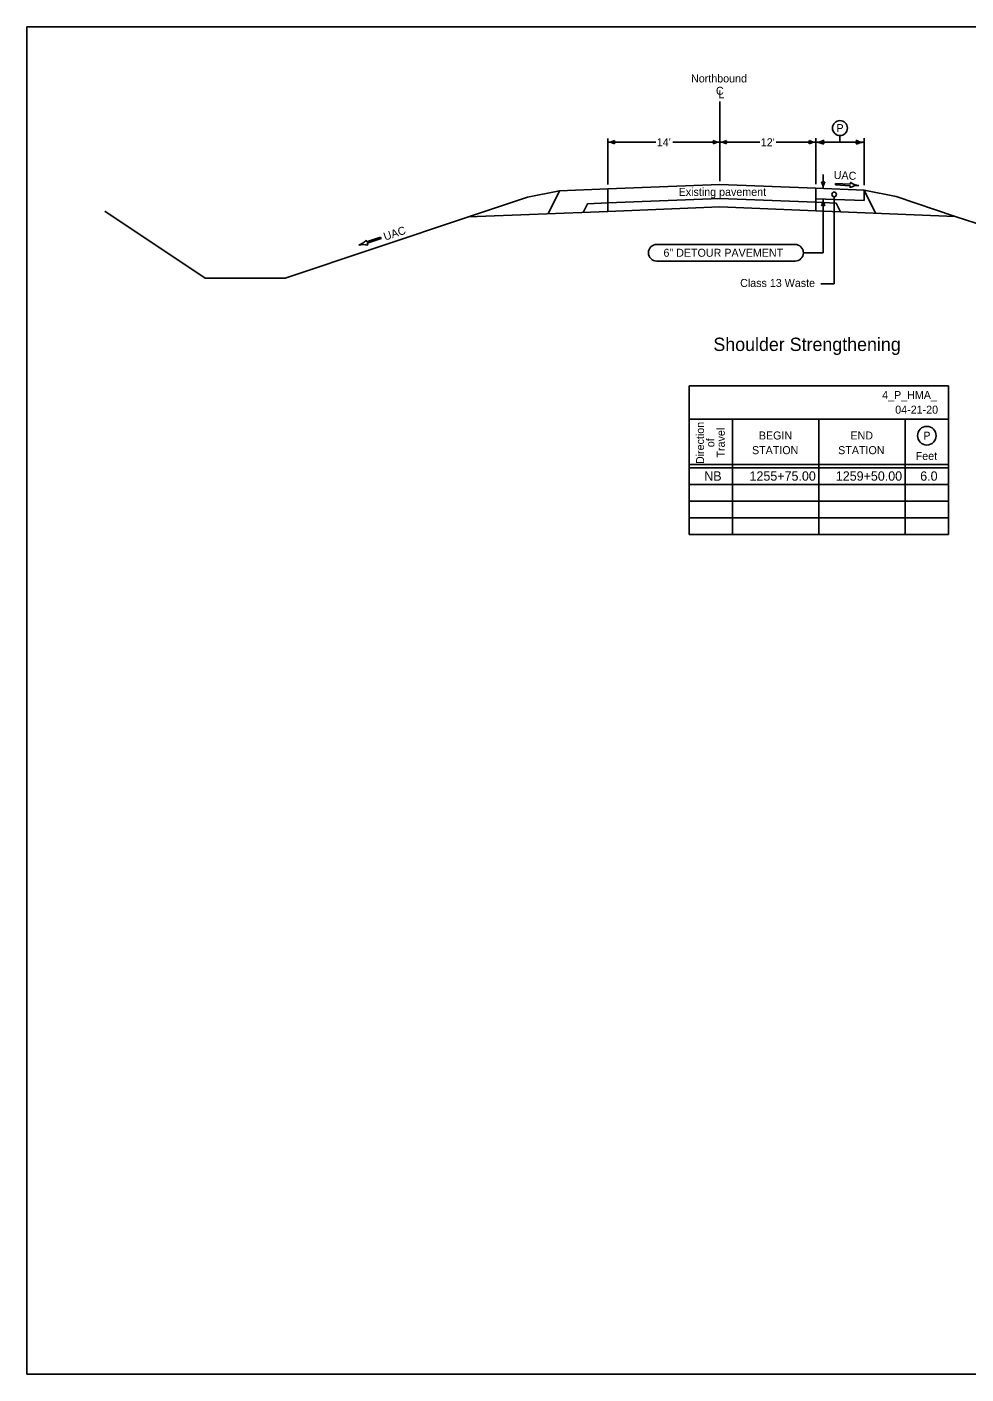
# Model space of a CAD drawing. Extents: x 10133 to 81668, y 7924 to 11018.
# Drawn here: x 10133 to 11541, y 7924 to 9944 of the extents above; entities that cross this region are included whole.
import ezdxf

# ---------------------------------------------------------------- set-up
doc = ezdxf.new("R2010")
doc.units = 0
for name, color, linetype in [('dsnCellsNorthArrow', 7, 'Continuous'), ('DsnShtRevisedText', 7, 'Continuous'), ('dsnStdNameDate', 7, 'Continuous'), ('dsnStdTable', 7, 'Continuous'), ('dsnTextFinalPlan', 7, 'Continuous'), ('dsnTextTabulation', 7, 'Continuous'), ('dsnXsPCCPavementBottom', 7, 'Continuous'), ('dsnXsShldrEarthFill', 7, 'Continuous'), ('dsnXsShldrSpecialBackBottom', 7, 'Continuous'), ('Level 6', 7, 'Continuous'), ('Level 7', 7, 'Continuous'), ('Level 8', 7, 'Continuous'), ('SheetAddendum', 7, 'Continuous'), ('SheetBorder', 7, 'Continuous')]:
    doc.layers.add(name, color=color, linetype=linetype)

# ---------------------------------------------------------------- blocks, each defined once
blk = doc.blocks.new('LT')
at = {"layer": 'dsnCellsNorthArrow'}
for centre, radius, start, end in [((-35.6, 0), 16.4, 342.2666, 17.7333), ((0, 42.5), 42.5, 241.9275, 270), ((0, -42.5), 42.5, 90, 118.0725)]:
    blk.add_arc(centre, radius, start, end, dxfattribs=at)

msp = doc.modelspace()

# ---------------------------------------------------------------- linework, layer by layer
at = {"layer": 'DsnShtRevisedText'}
for p, q in [((11345.7, 9709.5), (11345.6, 9707.1)), ((11345.6, 9707.1), (11367.6, 9705.8)), ((11367.7, 9708.2), (11345.7, 9709.5)), ((11367.6, 9705.8), (11367.4, 9703)), ((11367.9, 9711), (11367.7, 9708.2)), ((11380.4, 9706.3), (11380.4, 9706.3)), ((11343.6, 9558.7), (11343.6, 9689.4)), ((11077.4, 9617.9), (11284.9, 9617.9)), ((11284.9, 9617.9), (11077.4, 9617.9)), ((11284.9, 9592.9), (11077.4, 9592.9)), ((11284.9, 9592.9), (11077.4, 9592.9)), ((11323.4, 9558.7), (11343.6, 9558.7))]:
    msp.add_line(p, q, dxfattribs=at)
msp.add_circle((11343.6, 9692.9), 3.5, dxfattribs=at)
for centre, radius, start, end in [((11380, 9680.5), 25.8, 89.1159, 119.146), ((11382.9, 9732), 25.8, 234.3819, 264.4119), ((11077.4, 9605.4), 12.5, 90, 270), ((11077.4, 9605.4), 12.5, 90, 270), ((11284.9, 9605.4), 12.5, 270, 90), ((11284.9, 9605.4), 12.5, 270, 90)]:
    msp.add_arc(centre, radius, start, end, dxfattribs=at)
at = {"layer": 'dsnStdNameDate'}
for p, q in [((11316.1, 9702.1), (11388.5, 9699.2)), ((11316.1, 9702.1), (11316.1, 9686.4)), ((11388.5, 9699.2), (11388.5, 9683.6)), ((11316.1, 9686.4), (11388.5, 9683.6))]:
    msp.add_line(p, q, dxfattribs=at)
at = {"layer": 'dsnStdTable'}
for p, q in [((11126, 9183.1), (11126, 9406.1)), ((11126, 9406.1), (11515.3, 9406.1)), ((11515.3, 9183.1), (11515.3, 9406.1)), ((11126, 9356.1), (11515.3, 9356.1)), ((11191.3, 9183.1), (11191.3, 9356.1)), ((11320.6, 9356.1), (11320.6, 9183.1)), ((11450.3, 9183.1), (11450.3, 9356.1)), ((11126, 9288.1), (11515.3, 9288.1)), ((11126, 9283.1), (11515.3, 9283.1)), ((11126, 9258.1), (11515.3, 9258.1)), ((11126, 9233.1), (11515.3, 9233.1)), ((11126, 9208.1), (11515.3, 9208.1)), ((11126, 9183.1), (11515.3, 9183.1))]:
    msp.add_line(p, q, dxfattribs=at)
at = {"layer": 'dsnTextFinalPlan'}
for p, q in [((11316.1, 9702.1), (11316.1, 9686.4)), ((11388.5, 9699.2), (11316.1, 9702.1)), ((11388.5, 9683.6), (11388.5, 9699.2)), ((11316.1, 9686.4), (11388.5, 9683.6))]:
    msp.add_line(p, q, dxfattribs=at)
at = {"layer": 'dsnXsPCCPavementBottom'}
for p, q in [((11004.1, 9667.4), (11004.1, 9701.1)), ((11316.1, 9668.4), (11316.1, 9702.1)), ((11004.1, 9667.4), (10794.9, 9659.1)), ((11316.1, 9668.4), (11525.2, 9660))]:
    msp.add_line(p, q, dxfattribs=at)
at = {"layer": 'dsnXsShldrEarthFill'}
for p, q in [((10931.6, 9698.2), (10883.6, 9688.6)), ((11388.5, 9699.2), (11436.5, 9689.6)), ((10883.6, 9688.6), (10794.9, 9659.1)), ((11436.5, 9689.6), (11525.2, 9660)), ((10399.9, 9567.4), (10249.4, 9667.7)), ((10794.9, 9659.1), (10519.9, 9567.4)), ((11525.2, 9660), (11641, 9621.9)), ((10630.5, 9616.7), (10630.5, 9616.7)), ((10641.3, 9624.5), (10642.2, 9621.9)), ((10642.2, 9621.9), (10663.1, 9628.8)), ((10663.9, 9626.6), (10643, 9619.6)), ((10643, 9619.6), (10643.9, 9616.9)), ((10663.1, 9628.8), (10663.9, 9626.6)), ((10399.9, 9567.4), (10519.9, 9567.4))]:
    msp.add_line(p, q, dxfattribs=at)
for centre, start, end in [((10621.4, 9640.8), 290.787, 320.817), ((10637.6, 9591.9), 76.053, 106.083)]:
    msp.add_arc(centre, 25.8, start, end, dxfattribs=at)
at = {"layer": 'dsnXsShldrSpecialBackBottom'}
for p, q in [((10973.6, 9678.9), (10967.1, 9665.9)), ((11004.1, 9680.1), (10973.6, 9678.9)), ((11316.1, 9681.1), (11346.5, 9679.9)), ((11346.5, 9679.9), (11353, 9666.9))]:
    msp.add_line(p, q, dxfattribs=at)
at = {"layer": 'Level 6'}
for p, q in [((10931.6, 9698.2), (10914.4, 9663.8)), ((11004.1, 9701.1), (10931.6, 9698.2)), ((11316.1, 9702.1), (11388.5, 9699.2)), ((11388.5, 9699.2), (11405.7, 9664.8))]:
    msp.add_line(p, q, dxfattribs=at)
at = {"layer": 'Level 7'}
for p, q in [((11172.1, 9707.8), (11004.1, 9701.1)), ((11316.1, 9702.1), (11172.1, 9707.8)), ((11172.1, 9686.8), (11004.1, 9680.1)), ((11316.1, 9681.1), (11172.1, 9686.8)), ((11172.1, 9674.1), (11004.1, 9667.4)), ((11316.1, 9668.4), (11172.1, 9674.1))]:
    msp.add_line(p, q, dxfattribs=at)
at = {"layer": 'Level 8'}
for p, q in [((11172.1, 9724.3), (11172.1, 9832.2)), ((11004, 9776.9), (11004, 9707.9)), ((11316, 9708.1), (11316, 9777.1)), ((11316, 9708.1), (11316, 9776.9)), ((11352.3, 9771.1), (11352.3, 9781.1)), ((11388.5, 9706.6), (11388.5, 9777.1)), ((11076.2, 9771.1), (11004.1, 9771.1)), ((11172.1, 9771.1), (11101.7, 9771.1)), ((11232.3, 9771.1), (11172.1, 9771.1)), ((11316, 9771.1), (11256.8, 9771.1)), ((11388.5, 9771.1), (11316, 9771.1)), ((11172.1, 9712.7), (11172.1, 9724.3)), ((11327.2, 9722.8), (11327.2, 9701.6)), ((11327.2, 9686), (11327.2, 9605.4)), ((11297.4, 9605.4), (11327.2, 9605.4))]:
    msp.add_line(p, q, dxfattribs=at)
for centre, radius in [((11352.3, 9792.3), 11.2), ((11482.6, 9331.1), 14)]:
    msp.add_circle(centre, radius, dxfattribs=at)
for centre, radius, start, end in [((11004.1, 9792.4), 21.3, 270, 298.0725), ((11004.1, 9749.9), 21.3, 61.9275, 90), ((11021.9, 9771.1), 8.21, 162.2666, 197.7334), ((11154.2, 9771.1), 8.21, 342.2667, 17.7334), ((11172.1, 9792.4), 21.3, 241.9275, 270), ((11172.1, 9749.9), 21.3, 90, 118.0725), ((11172.1, 9792.4), 21.3, 270, 298.0725), ((11172.1, 9749.9), 21.3, 61.9275, 90), ((11189.9, 9771.1), 8.21, 162.2666, 197.7334), ((11298.2, 9771.1), 8.21, 342.2667, 17.7334), ((11316, 9792.4), 21.3, 241.9275, 270), ((11316, 9749.9), 21.3, 90, 118.0725), ((11327.2, 9719.5), 8.21, 252.2666, 287.7333), ((11305.9, 9701.6), 21.3, 0, 28.0725), ((11348.4, 9701.6), 21.3, 151.9275, 180), ((11305.9, 9686), 21.3, 331.9275, 360), ((11327.2, 9668.2), 8.21, 72.2666, 107.7334), ((11348.4, 9686), 21.3, 180, 208.0725)]:
    msp.add_arc(centre, radius, start, end, dxfattribs=at)
at = {"layer": 'SheetBorder'}
msp.add_lwpolyline([(10132.5, 9944), (13267.5, 9944), (13267.5, 7924), (10132.5, 7924)], close=True, dxfattribs=at)

# ---------------------------------------------------------------- block references
at = {"layer": 'Level 8', "xscale": 0.5999999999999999, "yscale": 0.5999999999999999, "rotation": 180}
msp.add_blockref('LT', (11316, 9771.1), dxfattribs=at)
at = {"layer": 'Level 8', "xscale": 0.5999999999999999, "yscale": 0.5999999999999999}
msp.add_blockref('LT', (11388.5, 9771.1), dxfattribs=at)

# ---------------------------------------------------------------- texts
at = {"layer": 'DsnShtRevisedText'}
msp.add_text('UAC', height=12, rotation=357.0784, dxfattribs=at).set_placement((11342.7, 9716.3))
for s, height, p in [('6" DETOUR PAVEMENT', 12, (11087.5, 9599.4)), ('Class 13 Waste', 12, (11202.5, 9554.1)), ('Shoulder Strengthening', 20, (11162.4, 9458.1))]:
    msp.add_text(s, height=height, dxfattribs=at).set_placement(p)
at = {"layer": 'dsnStdTable'}
for s, p in [('Direction', (11148.4, 9288.6)), ('Travel', (11179.5, 9298.4)), ('of', (11163.9, 9313.8))]:
    msp.add_text(s, height=12, rotation=90, dxfattribs=at).set_placement(p)
for s, p in [('BEGIN', (11230.6, 9325.4)), ('END', (11368, 9325.4)), ('STATION', (11220.3, 9303.4)), ('STATION', (11349.6, 9303.4)), ('Feet', (11465.9, 9294.7))]:
    msp.add_text(s, height=12, dxfattribs=at).set_placement(p)
at = {"layer": 'dsnTextTabulation'}
for s, p in [('4_P_HMA_   ', (11415.6, 9386.1)), ('04-21-20', (11435.2, 9364.1))]:
    msp.add_text(s, height=12, dxfattribs=at).set_placement(p)
at = {"layer": 'dsnXsShldrEarthFill'}
msp.add_text('UAC', height=12, rotation=18.435, dxfattribs=at).set_placement((10669.9, 9623.5))
at = {"layer": 'Level 7'}
msp.add_text('Existing pavement', height=12, dxfattribs=at).set_placement((11110.3, 9690.7))
at = {"layer": 'Level 8'}
for s, p in [('Northbound', (11128.9, 9860.8)), ('C', (11166.2, 9842.3)), ('L', (11169.9, 9837.1)), ('P', (11347, 9786.3)), ("14'", (11077.5, 9765.1)), ("12'", (11233.5, 9765.1)), ('P', (11477.4, 9325.1))]:
    msp.add_text(s, height=12, dxfattribs=at).set_placement(p)
at = {"layer": 'SheetAddendum'}
for s, p in [('NB', (11148.7, 9263.6)), ('1255+75.00', (11216.6, 9263.6)), ('1259+50.00', (11346.1, 9263.6)), ('6.0', (11472.7, 9263.6))]:
    msp.add_text(s, height=14, dxfattribs=at).set_placement(p)

doc.saveas('drawing.dxf')
